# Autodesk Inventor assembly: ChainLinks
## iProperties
Author: Administrator
Shininess: 0.0
Length Units: 11272
Angle Units: 11286
Time Units: 11279
Mass Units: 11290
Length Display Precision: 3
Angle Display Precision: 2
Compacted: True
PropertySet Name: _Private Model Information
Created: 2000-09
Part Number: ChainLinks
Document SubType Name: Assembly
Designer: Administrator
Control State: 0
Master: False
Checked Out: False
PropertySet Name: Design Tracking Control
Density: 0.0
Volumn: 0.0
Area: 0.0
PropertySet Name: Model Information
